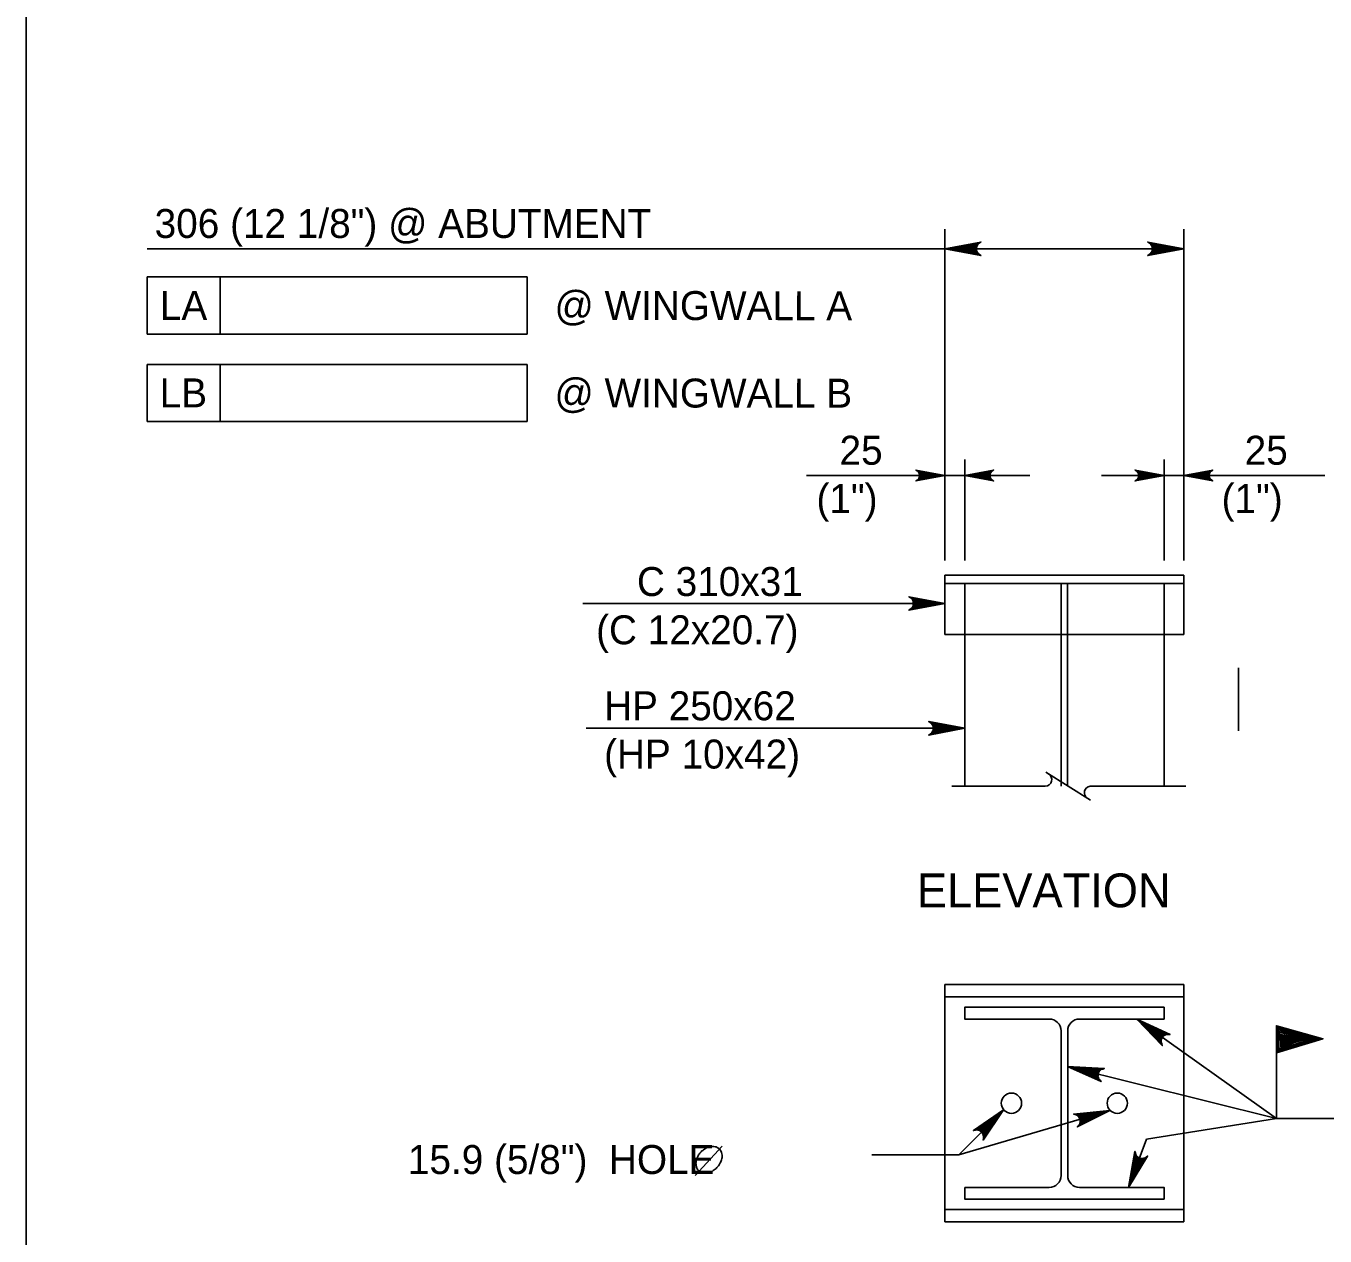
# Model space of a CAD drawing. Extents: x 635440 to 640306, y 296653 to 298484.
# Drawn here: x 639316.5 to 639451, y 297539.6 to 297665 of the extents above; entities that cross this region are included whole.
import ezdxf

# ---------------------------------------------------------------- set-up
doc = ezdxf.new("R2010")
doc.units = 0
for name, color, linetype in [('1', 7, 'Continuous'), ('2', 7, 'Continuous'), ('3', 7, 'Continuous'), ('4', 7, 'Continuous'), ('5', 7, 'Continuous')]:
    doc.layers.add(name, color=color, linetype=linetype)

# ---------------------------------------------------------------- blocks, each defined once
blk = doc.blocks.new('HPILE')
at = {"layer": '3'}
for p, q in [((-0.122, -2.665), (-0.122, 2.665)), ((0.122, 2.665), (0.122, -2.665)), ((-3.673, -3.102), (-0.56, -3.102))]:
    blk.add_line(p, q, dxfattribs=at)
for points in [[(-0.56, 3.102), (-3.673, 3.102), (-3.673, 3.537), (3.673, 3.537), (3.673, 3.102), (0.56, 3.102)], [(0.56, -3.102), (3.673, -3.102), (3.673, -3.536), (-3.673, -3.536), (-3.673, -3.102)]]:
    blk.add_lwpolyline(points, dxfattribs=at)
for centre, start, end in [((-0.56, 2.665), 0, 90), ((0.56, 2.665), 90, 180), ((-0.56, -2.665), 270, 0), ((0.56, -2.665), 180, 270)]:
    blk.add_arc(centre, 0.438, start, end, dxfattribs=at)
blk = doc.blocks.new('LT')
at = {"layer": '1'}
blk.add_lwpolyline([(0, 0), (-11.18, -2.1), (-10.75, -1.8), (-10.32, -1.5), (-10.1, -1.12), (-9.88, -0.75), (-9.81, -0.38), (-9.75, 0), (-9.81, 0.38), (-9.88, 0.75), (-10.1, 1.12), (-10.32, 1.5), (-10.75, 1.8), (-11.18, 2.1), (0, 0), (-10.75, 1.8), (-10.32, 1.5), (0, 0), (-10.1, 1.12), (-9.88, 0.75), (0, 0), (-9.81, 0.38), (-9.75, 0), (0, 0), (-9.81, -0.38), (-9.88, -0.75), (0, 0), (-10.1, -1.12), (-10.32, -1.5), (0, 0), (-10.75, -1.8)], dxfattribs=at)

msp = doc.modelspace()

# ---------------------------------------------------------------- linework, layer by layer
at = {"layer": '2'}
msp.add_line((639316.46, 297262.46), (639316.46, 297826.46), dxfattribs=at)
at = {"layer": '3'}
for p, q in [((639411.61, 297608.09), (639411.61, 297601.94)), ((639411.61, 297608.09), (639436.35, 297608.09)), ((639411.61, 297607.23), (639436.35, 297607.23)), ((639413.66, 297607.23), (639413.66, 297601.94)), ((639423.64, 297607.23), (639423.64, 297586.22)), ((639424.32, 297607.23), (639424.32, 297586.22)), ((639434.3, 297607.23), (639434.3, 297601.94)), ((639436.35, 297601.94), (639436.35, 297608.09)), ((639411.61, 297601.94), (639436.35, 297601.94)), ((639413.66, 297601.94), (639413.66, 297586.22)), ((639434.3, 297586.22), (639434.3, 297601.94)), ((639442.01, 297591.94), (639442.01, 297598.49)), ((639422.05, 297587.68), (639426.67, 297584.77)), ((639412.33, 297586.22), (639422, 297586.22)), ((639426.66, 297586.22), (639436.55, 297586.22)), ((639411.61, 297565.68), (639436.35, 297565.68)), ((639411.61, 297565.68), (639411.61, 297541.08)), ((639436.35, 297541.08), (639436.35, 297565.68)), ((639411.61, 297564.4), (639436.35, 297564.4)), ((639445.94, 297551.8), (639424.32, 297557.18)), ((639445.94, 297551.8), (639432.5, 297549.65)), ((639445.94, 297551.8), (639475.58, 297551.8)), ((639432.5, 297549.65), (639430.62, 297544.66)), ((639411.61, 297542.36), (639436.35, 297542.36)), ((639411.61, 297541.08), (639436.35, 297541.08))]:
    msp.add_line(p, q, dxfattribs=at)
for points in [[(639431.49, 297562.1), (639445.94, 297551.8)], [(639445.94, 297551.8), (639445.94, 297561.4), (639450.75, 297560.06), (639445.93, 297558.59), (639446.02, 297561.24), (639450.36, 297560.06), (639446.05, 297558.78), (639446.05, 297561.12), (639450.1, 297560.08), (639446.13, 297558.9), (639446.12, 297560.98), (639449.77, 297560.06), (639446.19, 297559.03), (639446.18, 297560.81), (639449.35, 297560.08), (639446.46, 297559.34), (639446.27, 297560.69), (639449.08, 297560.11), (639446.4, 297559.2), (639446.36, 297560.51), (639448.8, 297560.11), (639446.5, 297559.4), (639446.44, 297560.39), (639448.49, 297560.11), (639446.58, 297559.49), (639446.5, 297560.33), (639448.22, 297560.11), (639446.61, 297559.58), (639446.61, 297560.2), (639447.96, 297560.1), (639446.69, 297559.71), (639446.69, 297560.13), (639447.59, 297560.05), (639446.74, 297559.79), (639446.77, 297560), (639447.31, 297560.02), (639446.75, 297559.85), (639446.8, 297559.96), (639450.58, 297560.06), (639446.01, 297558.7), (639445.99, 297561.32)]]:
    msp.add_lwpolyline(points, dxfattribs=at)
for centre in [(639418.5, 297553.38), (639429.46, 297553.38)]:
    msp.add_circle(centre, 1.05, dxfattribs=at)
for centre, start, end in [((639422, 297586.91), 270, 60), ((639426.73, 297585.54), 95.3286, 237.8672)]:
    msp.add_arc(centre, 0.682, start, end, dxfattribs=at)
at = {"layer": '4'}
for p, q in [((639411.61, 297643.92), (639411.61, 297609.61)), ((639436.35, 297643.92), (639436.35, 297609.61)), ((639411.61, 297641.89), (639328.99, 297641.89)), ((639436.35, 297641.89), (639411.61, 297641.89)), ((639328.99, 297638.97), (639368.36, 297638.97)), ((639328.99, 297638.97), (639328.99, 297633.06)), ((639336.55, 297638.97), (639336.55, 297633.06)), ((639368.36, 297638.97), (639368.36, 297633.06)), ((639328.99, 297633.06), (639368.36, 297633.06)), ((639328.99, 297629.91), (639368.36, 297629.91)), ((639328.99, 297629.91), (639328.99, 297624)), ((639336.55, 297629.91), (639336.55, 297624)), ((639368.36, 297629.91), (639368.36, 297624)), ((639328.99, 297624), (639368.36, 297624)), ((639413.66, 297620.06), (639413.66, 297609.61)), ((639434.3, 297620.06), (639434.3, 297609.61)), ((639420.4, 297618.41), (639397.27, 297618.41)), ((639450.96, 297618.41), (639427.83, 297618.41))]:
    msp.add_line(p, q, dxfattribs=at)
for points in [[(639411.61, 297641.89), (639415.34, 297642.59), (639415.19, 297642.49), (639415.05, 297642.39), (639414.98, 297642.27), (639414.9, 297642.14), (639414.88, 297642.02), (639414.86, 297641.89), (639414.88, 297641.77), (639414.9, 297641.64), (639414.98, 297641.52), (639415.05, 297641.39), (639415.19, 297641.29), (639415.34, 297641.19), (639411.61, 297641.89), (639415.19, 297641.29), (639415.05, 297641.39), (639411.61, 297641.89), (639414.98, 297641.52), (639414.9, 297641.64), (639411.61, 297641.89), (639414.88, 297641.77), (639414.86, 297641.89), (639411.61, 297641.89), (639414.88, 297642.02), (639414.9, 297642.14), (639411.61, 297641.89), (639414.98, 297642.27), (639415.05, 297642.39), (639411.61, 297641.89), (639415.19, 297642.49)], [(639436.35, 297641.89), (639432.62, 297641.19), (639432.77, 297641.29), (639432.91, 297641.39), (639432.98, 297641.52), (639433.06, 297641.64), (639433.08, 297641.77), (639433.1, 297641.89), (639433.08, 297642.02), (639433.06, 297642.14), (639432.98, 297642.27), (639432.91, 297642.39), (639432.77, 297642.49), (639432.62, 297642.59), (639436.35, 297641.89), (639432.77, 297642.49), (639432.91, 297642.39), (639436.35, 297641.89), (639432.98, 297642.27), (639433.06, 297642.14), (639436.35, 297641.89), (639433.08, 297642.02), (639433.1, 297641.89), (639436.35, 297641.89), (639433.08, 297641.77), (639433.06, 297641.64), (639436.35, 297641.89), (639432.98, 297641.52), (639432.91, 297641.39), (639436.35, 297641.89), (639432.77, 297641.29)], [(639411.61, 297605.15), (639407.88, 297604.45), (639408.02, 297604.55), (639408.17, 297604.65), (639408.24, 297604.77), (639408.32, 297604.9), (639408.34, 297605.02), (639408.36, 297605.15), (639408.34, 297605.27), (639408.32, 297605.4), (639408.24, 297605.52), (639408.17, 297605.65), (639408.02, 297605.75), (639407.88, 297605.85), (639411.61, 297605.15), (639408.02, 297605.75), (639408.17, 297605.65), (639411.61, 297605.15), (639408.24, 297605.52), (639408.32, 297605.4), (639411.61, 297605.15), (639408.34, 297605.27), (639408.36, 297605.15), (639411.61, 297605.15), (639408.34, 297605.02), (639408.32, 297604.9), (639411.61, 297605.15), (639408.24, 297604.77), (639408.17, 297604.65), (639411.61, 297605.15), (639408.02, 297604.55)], [(639411.61, 297605.15), (639374.13, 297605.15)], [(639413.66, 297592.22), (639409.93, 297591.52), (639410.07, 297591.62), (639410.22, 297591.72), (639410.29, 297591.85), (639410.37, 297591.97), (639410.39, 297592.1), (639410.41, 297592.22), (639410.39, 297592.35), (639410.37, 297592.47), (639410.29, 297592.6), (639410.22, 297592.72), (639410.07, 297592.82), (639409.93, 297592.92), (639413.66, 297592.22), (639410.07, 297592.82), (639410.22, 297592.72), (639413.66, 297592.22), (639410.29, 297592.6), (639410.37, 297592.47), (639413.66, 297592.22), (639410.39, 297592.35), (639410.41, 297592.22), (639413.66, 297592.22), (639410.39, 297592.1), (639410.37, 297591.97), (639413.66, 297592.22), (639410.29, 297591.85), (639410.22, 297591.72), (639413.66, 297592.22), (639410.07, 297591.62)], [(639413.66, 297592.22), (639374.46, 297592.22)], [(639431.49, 297562.09), (639434.93, 297560.5), (639434.75, 297560.5), (639434.58, 297560.5), (639434.45, 297560.45), (639434.31, 297560.39), (639434.22, 297560.3), (639434.13, 297560.21), (639434.08, 297560.09), (639434.02, 297559.98), (639434.01, 297559.84), (639434, 297559.69), (639434.06, 297559.53), (639434.12, 297559.36), (639431.49, 297562.09), (639434.06, 297559.53), (639434, 297559.69), (639431.49, 297562.09), (639434.01, 297559.84), (639434.02, 297559.98), (639431.49, 297562.09), (639434.08, 297560.09), (639434.13, 297560.21), (639431.49, 297562.09), (639434.22, 297560.3), (639434.31, 297560.39), (639431.49, 297562.09), (639434.45, 297560.45), (639434.58, 297560.5), (639431.49, 297562.09), (639434.75, 297560.5)], [(639424.32, 297557.18), (639428.11, 297556.99), (639427.95, 297556.92), (639427.79, 297556.86), (639427.68, 297556.76), (639427.58, 297556.65), (639427.53, 297556.53), (639427.48, 297556.42), (639427.47, 297556.29), (639427.46, 297556.17), (639427.51, 297556.03), (639427.55, 297555.89), (639427.67, 297555.76), (639427.78, 297555.63), (639424.32, 297557.18), (639427.67, 297555.76), (639427.55, 297555.89), (639424.32, 297557.18), (639427.51, 297556.03), (639427.46, 297556.17), (639424.32, 297557.18), (639427.47, 297556.29), (639427.48, 297556.42), (639424.32, 297557.18), (639427.53, 297556.53), (639427.58, 297556.65), (639424.32, 297557.18), (639427.68, 297556.76), (639427.79, 297556.86), (639424.32, 297557.18), (639427.95, 297556.92)], [(639417.69, 297552.71), (639413.04, 297548.02), (639404.04, 297548.02)], [(639428.7, 297552.64), (639413.04, 297548.02)], [(639417.69, 297552.71), (639415.56, 297549.57), (639415.59, 297549.74), (639415.62, 297549.91), (639415.58, 297550.05), (639415.55, 297550.19), (639415.47, 297550.3), (639415.4, 297550.4), (639415.29, 297550.47), (639415.19, 297550.54), (639415.05, 297550.58), (639414.91, 297550.61), (639414.74, 297550.58), (639414.57, 297550.55), (639417.69, 297552.71), (639414.74, 297550.58), (639414.91, 297550.61), (639417.69, 297552.71), (639415.05, 297550.58), (639415.19, 297550.54), (639417.69, 297552.71), (639415.29, 297550.47), (639415.4, 297550.4), (639417.69, 297552.71), (639415.47, 297550.3), (639415.55, 297550.19), (639417.69, 297552.71), (639415.58, 297550.05), (639415.62, 297549.91), (639417.69, 297552.71), (639415.59, 297549.74)], [(639428.7, 297552.64), (639425.32, 297550.92), (639425.43, 297551.05), (639425.54, 297551.19), (639425.58, 297551.33), (639425.61, 297551.47), (639425.6, 297551.6), (639425.58, 297551.72), (639425.53, 297551.84), (639425.47, 297551.95), (639425.37, 297552.05), (639425.26, 297552.15), (639425.09, 297552.2), (639424.93, 297552.26), (639428.7, 297552.64), (639425.09, 297552.2), (639425.26, 297552.15), (639428.7, 297552.64), (639425.37, 297552.05), (639425.47, 297551.95), (639428.7, 297552.64), (639425.53, 297551.84), (639425.58, 297551.72), (639428.7, 297552.64), (639425.6, 297551.6), (639425.61, 297551.47), (639428.7, 297552.64), (639425.58, 297551.33), (639425.54, 297551.19), (639428.7, 297552.64), (639425.43, 297551.05)], [(639430.62, 297544.66), (639431.29, 297548.39), (639431.33, 297548.23), (639431.37, 297548.06), (639431.46, 297547.94), (639431.55, 297547.83), (639431.66, 297547.76), (639431.77, 297547.7), (639431.9, 297547.67), (639432.02, 297547.65), (639432.16, 297547.68), (639432.31, 297547.7), (639432.45, 297547.8), (639432.59, 297547.9), (639430.62, 297544.66), (639432.45, 297547.8), (639432.31, 297547.7), (639430.62, 297544.66), (639432.16, 297547.68), (639432.02, 297547.65), (639430.62, 297544.66), (639431.9, 297547.67), (639431.77, 297547.7), (639430.62, 297544.66), (639431.66, 297547.76), (639431.55, 297547.83), (639430.62, 297544.66), (639431.46, 297547.94), (639431.37, 297548.06), (639430.62, 297544.66), (639431.33, 297548.23)]]:
    msp.add_lwpolyline(points, dxfattribs=at)
at = {"layer": '5'}
msp.add_line((639385.74, 297545.88), (639388.55, 297548.94), dxfattribs=at)
msp.add_spline([(639388.25, 297548.64), (639388.03, 297548.81), (639387.82, 297548.87), (639387.54, 297548.9), (639387.38, 297548.9), (639387.12, 297548.83), (639386.87, 297548.72), (639386.7, 297548.62), (639386.37, 297548.36), (639386.11, 297548.02), (639385.95, 297547.7), (639385.86, 297547.41), (639385.83, 297547.15), (639385.86, 297546.91), (639385.97, 297546.58), (639386.09, 297546.41), (639386.33, 297546.23), (639386.7, 297546.15), (639387.11, 297546.16), (639387.63, 297546.4), (639388.01, 297546.72), (639388.3, 297547.12), (639388.48, 297547.53), (639388.55, 297548), (639388.47, 297548.29), (639388.27, 297548.64)], degree=3, dxfattribs=at)

# ---------------------------------------------------------------- block references
at = {"layer": '3', "xscale": 2.8100040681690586, "yscale": 2.8100040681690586}
msp.add_blockref('HPILE', (639423.98, 297553.38), dxfattribs=at)
at = {"layer": '4', "xscale": 0.2682316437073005, "yscale": 0.2682366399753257}
for p in [(639411.61, 297618.41), (639411.61, 297618.41), (639434.3, 297618.41), (639434.3, 297618.41)]:
    msp.add_blockref('LT', p, dxfattribs=at)
at = {"layer": '4', "xscale": 0.2682316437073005, "yscale": 0.2682366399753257, "rotation": 180}
for p in [(639413.66, 297618.41), (639413.66, 297618.41), (639436.35, 297618.41), (639436.35, 297618.41)]:
    msp.add_blockref('LT', p, dxfattribs=at)

# ---------------------------------------------------------------- texts
at = {"layer": '4'}
for s, height, p in [('306 (12 1/8") @ ABUTMENT', 3.0001, (639329.78, 297643.01)), ('LA', 3, (639330.32, 297634.52)), ('LB', 3, (639330.3, 297625.46)), ('25', 3, (639400.7, 297619.52)), ('25', 3, (639442.65, 297619.52)), ('(1")', 3, (639398.31, 297614.52)), ('(1")', 3, (639440.26, 297614.52)), ('C 310x31', 3, (639379.72, 297605.92)), ('(C 12x20.7)', 3.0001, (639375.49, 297600.92)), ('HP 250x62', 3, (639376.32, 297593.05)), ('(HP 10x42)', 3, (639376.32, 297588.05)), ('ELEVATION', 3.5, (639408.71, 297573.68)), ('15.9 (5/8")  HOLE', 3.0001, (639356, 297546.05))]:
    msp.add_text(s, height=height, dxfattribs=at).set_placement(p)
for s, p in [('@ WINGWALL A', (639371.18, 297634.52)), ('@ WINGWALL B', (639371.18, 297625.46))]:
    msp.add_text(s, height=3.0001, rotation=359.9382, dxfattribs=at).set_placement(p)

doc.saveas('drawing.dxf')
